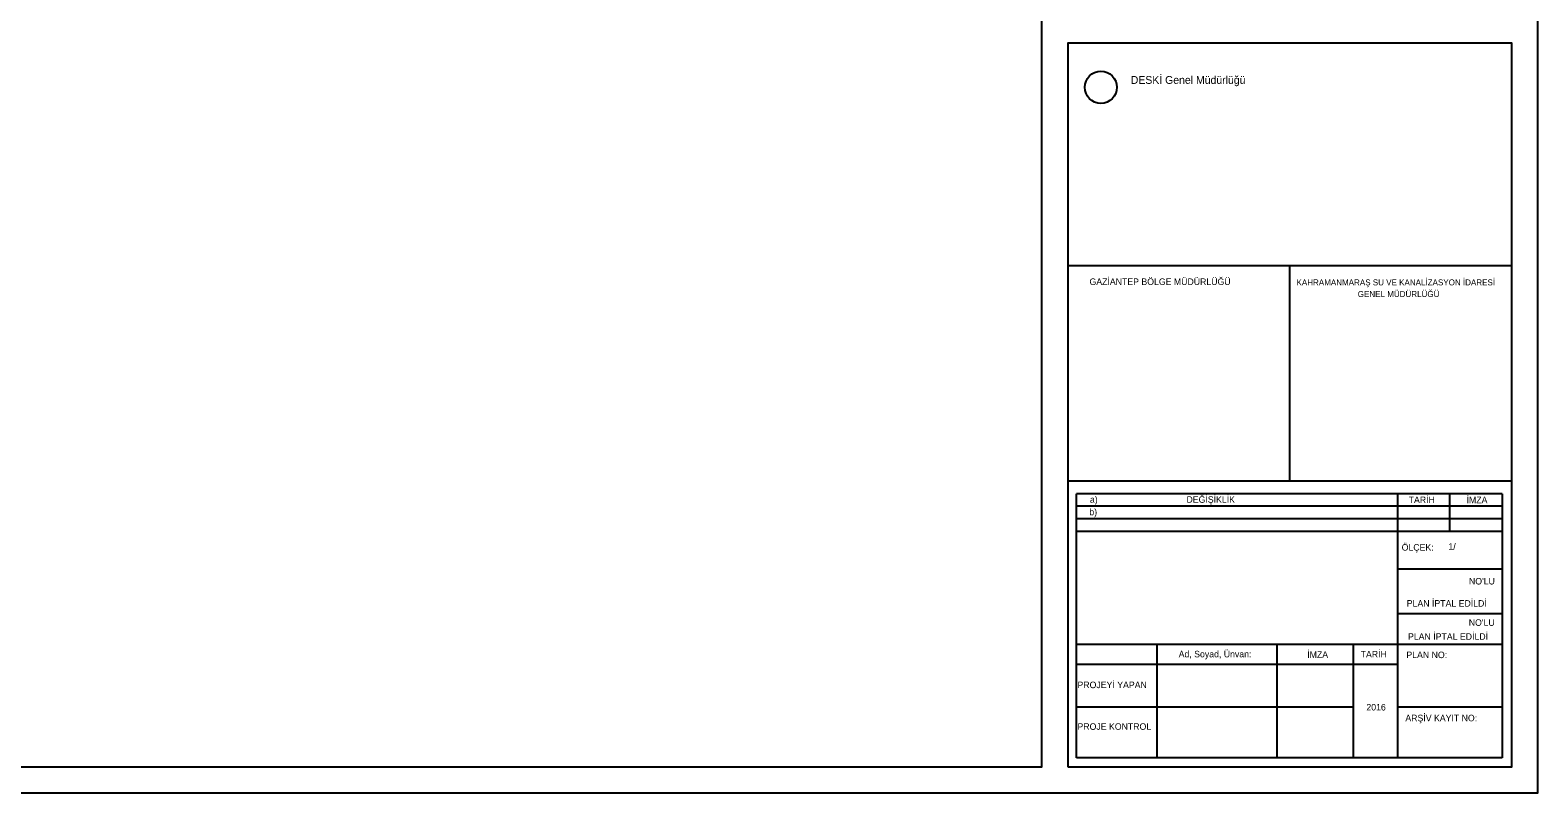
# Model space of a CAD drawing. Extents: x -10 to 1145, y -10 to 821.
# Drawn here: x 568 to 1145, y -10 to 282 of the extents above; entities that cross this region are included whole.
import ezdxf

# ---------------------------------------------------------------- set-up
doc = ezdxf.new("R2010")
doc.units = 0
for name, color, linetype in [('Baslik', 7, 'Continuous'), ('Default', 7, 'Continuous'), ('Level 50', 7, 'Continuous'), ('Level 51', 7, 'Continuous'), ('Level 53', 7, 'Continuous')]:
    doc.layers.add(name, color=color, linetype=linetype)

msp = doc.modelspace()

# ---------------------------------------------------------------- linework, layer by layer
at = {"layer": 'Baslik'}
for p, q in [((965, 191.88), (1135, 191.88)), ((1050, 109.32), (1050, 191.88)), ((1131.33, 109.32), (965, 109.32)), ((1131.33, 104.51), (968.31, 104.51)), ((968.31, 3.37), (968.31, 104.51)), ((1091.33, 3.37), (1091.33, 104.51)), ((1111.33, 90.08), (1111.33, 104.51)), ((1134.48, 109.32), (1131.33, 109.32)), ((1131.33, 104.51), (1131.33, 3.37)), ((1131.33, 99.7), (968.31, 99.7)), ((1131.33, 94.89), (968.31, 94.89)), ((1131.33, 90.08), (968.31, 90.08)), ((1131.33, 75.65), (1091.33, 75.65)), ((1131.33, 58.53), (1091.33, 58.53)), ((1131.33, 46.8), (968.31, 46.8)), ((999.2, 3.37), (999.2, 46.8)), ((1045.17, 3.37), (1045.17, 46.8)), ((1074.33, 3.37), (1074.33, 46.8)), ((1091.33, 39.11), (968.31, 39.11)), ((1074.33, 22.76), (968.31, 22.76)), ((1131.33, 22.76), (1091.33, 22.76)), ((1131.33, 3.37), (968.31, 3.37))]:
    msp.add_line(p, q, dxfattribs=at)
at = {"layer": 'Default'}
msp.add_circle((977.64, 260.12), 6.15, dxfattribs=at)
at = {"layer": 'Level 50'}
msp.add_lwpolyline([(0, 0), (955, 0), (955, 811), (0, 811)], close=True, dxfattribs=at)
at = {"layer": 'Level 51'}
msp.add_lwpolyline([(-10, -10), (1145, -10), (1145, 821), (-10, 821)], close=True, dxfattribs=at)
at = {"layer": 'Level 53'}
msp.add_lwpolyline([(965, 0), (1135, 0), (1135, 277), (965, 277)], close=True, dxfattribs=at)

# ---------------------------------------------------------------- texts
at = {"layer": 'Baslik'}
for s, height, p in [('DESKİ Genel Müdürlüğü', 3, (989.08, 261.44)), ('GAZİANTEP BÖLGE MÜDÜRLÜĞÜ', 2.5, (973.27, 184.45)), ('KAHRAMANMARAŞ SU VE KANALİZASYON İDARESİ', 2.3, (1052.56, 184.28)), ('GENEL MÜDÜRLÜĞÜ', 2.3, (1076.02, 179.81)), ('DEĞİŞİKLİK', 2.5, (1010.41, 101.05)), ('TARİH', 2.5, (1095.52, 100.93)), ('İMZA', 2.5, (1117.7, 100.88)), ('b)', 2.5, (973.21, 96.28)), ('a)', 2.5, (973.43, 101.05)), ('ÖLÇEK:', 2.5, (1092.84, 82.73)), ('1/     ', 2.5, (1110.76, 83.06)), ("NO'LU", 2.5, (1118.61, 69.77)), ('PLAN İPTAL EDİLDİ', 2.5, (1094.79, 61.28)), ("NO'LU", 2.5, (1118.54, 53.94)), ('PLAN İPTAL EDİLDİ', 2.5, (1095.27, 48.58)), ('Ad, Soyad, Ünvan:', 2.5, (1007.42, 41.87)), ('İMZA', 2.5, (1056.67, 41.66)), ('TARİH', 2.5, (1077.13, 41.82)), ('PLAN NO:', 2.5, (1094.65, 41.58)), ('PROJEYİ YAPAN', 2.5, (968.66, 30.08)), ('2016', 2.5, (1079.32, 21.53)), ('ARŞİV KAYIT NO:', 2.5, (1094.26, 17.39)), ('PROJE KONTROL', 2.5, (968.66, 14.13))]:
    msp.add_text(s, height=height, dxfattribs=at).set_placement(p)

doc.saveas('drawing.dxf')
